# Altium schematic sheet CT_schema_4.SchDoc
size 574 x 363 mm
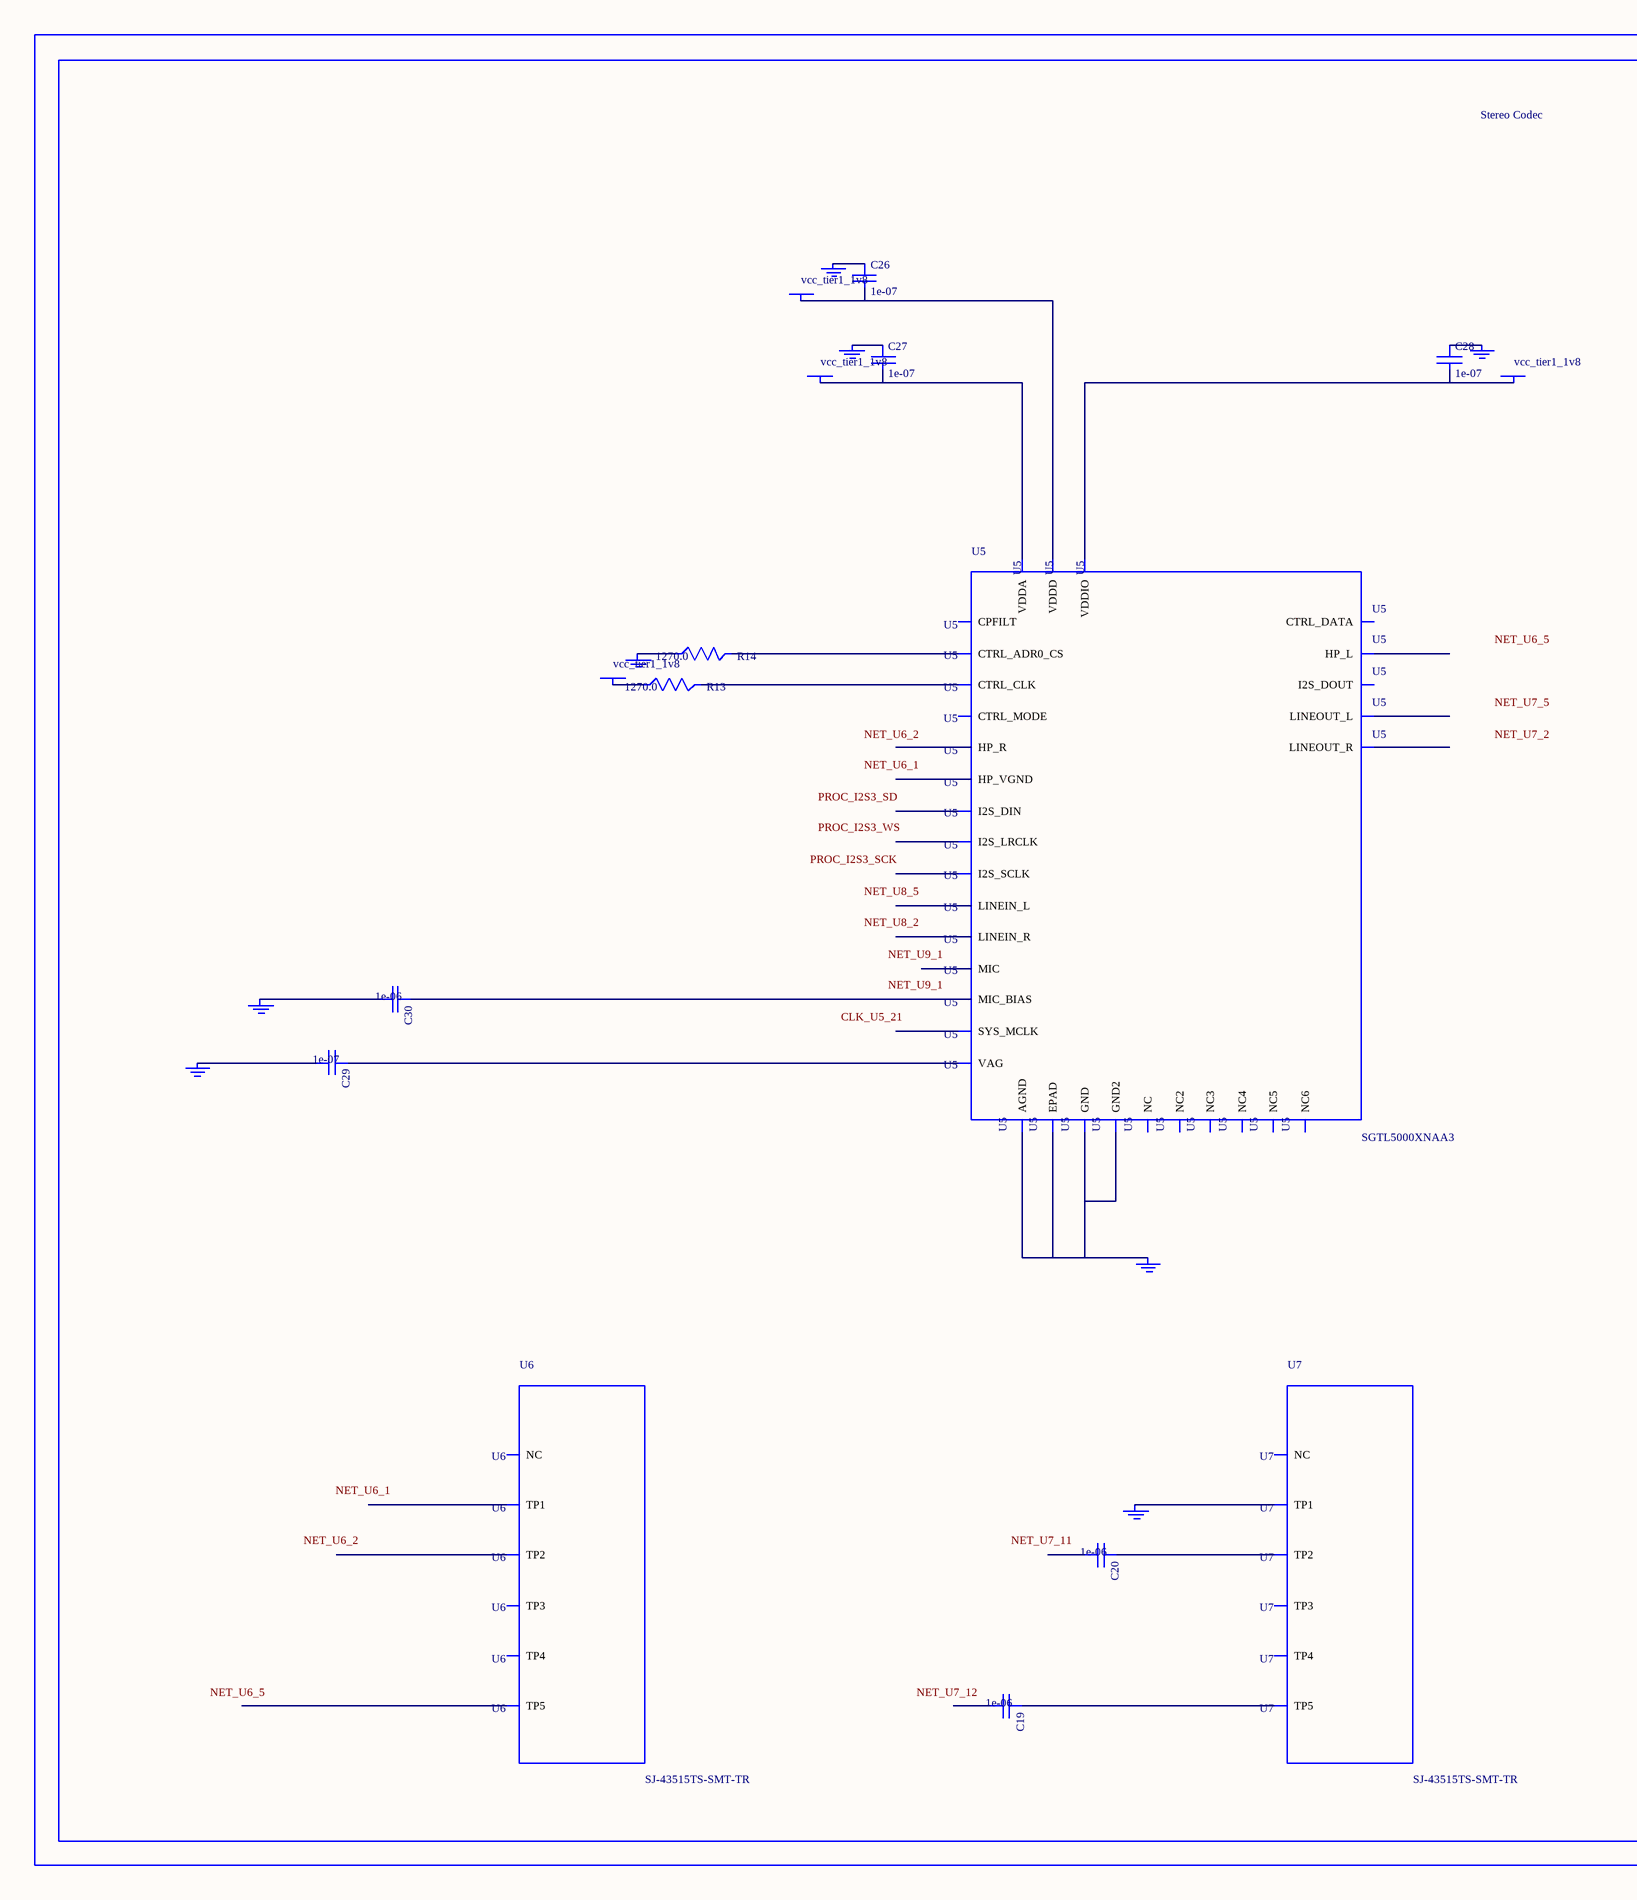
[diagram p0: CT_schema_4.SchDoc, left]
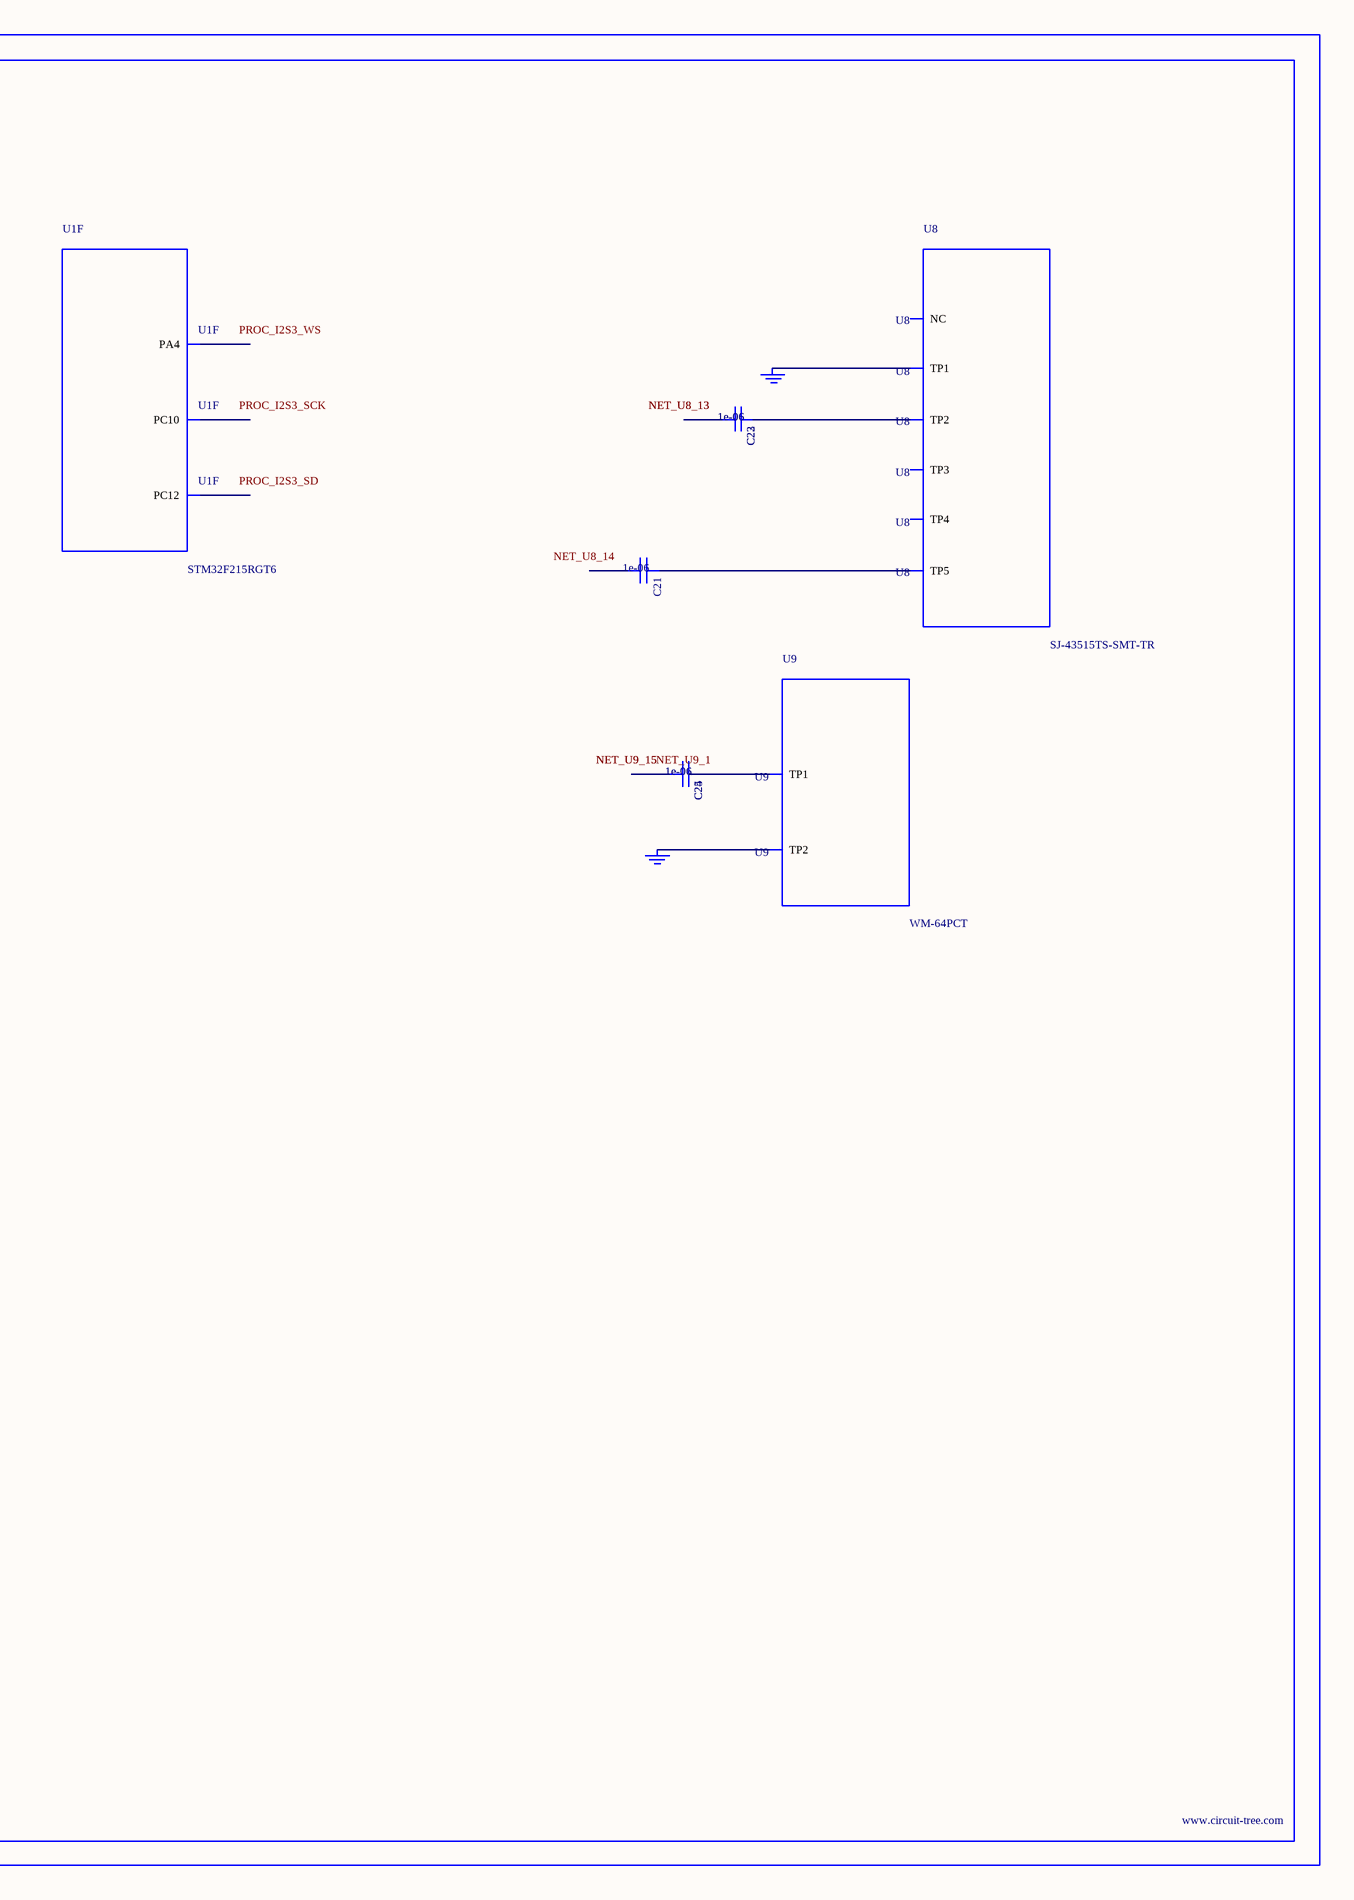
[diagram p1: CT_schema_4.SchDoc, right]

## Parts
BORDER3  (no value)
C19  1e-06  [C0603]
C20  1e-06  [C0603]
C21  1e-06  [C0603]
C22  1e-06  [C0603]
C23  1e-06  [C0603]
C24  1e-06  [C0603]
C25  1e-06  [C0603]
C26  1e-07  [C0402]
C27  1e-07  [C0402]
C28  1e-07  [C0402]
C29  1e-07  [C0402]
C30  1e-06  [C0603]
GND_INSTANCE_3_0  (no value)
GND_INSTANCE_3_1  (no value)
GND_INSTANCE_3_2  (no value)
GND_INSTANCE_3_3  (no value)
GND_INSTANCE_3_4  (no value)
GND_INSTANCE_3_5  (no value)
GND_INSTANCE_3_6  (no value)
GND_INSTANCE_3_7  (no value)
GND_INSTANCE_3_8  (no value)
GND_INSTANCE_3_9  (no value)
GND_INSTANCE_3_10  (no value)
POWER_INSTANCE_3_0  vcc_tier1_1v8
POWER_INSTANCE_3_1  vcc_tier1_1v8
POWER_INSTANCE_3_2  vcc_tier1_1v8
POWER_INSTANCE_3_3  vcc_tier1_1v8
R13  1270.0  [R0603]
R14  1270.0  [R0603]
U1  STM32F215RGT6  [LQFP64]  (part F of 7)
U5  SGTL5000XNAA3  [QFN-32]
U6  SJ-43515TS-SMT-TR  [SJ-43515TS-SMT-TR]
U7  SJ-43515TS-SMT-TR  [SJ-43515TS-SMT-TR]
U8  SJ-43515TS-SMT-TR  [SJ-43515TS-SMT-TR]
U9  WM-64PCT  [WM-64PC]

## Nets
NetC19_1: C19.1 U7.5(TP5)
NetC20_1: C20.1 U7.2(TP2)
NetC21_1: C21.1 U8.5(TP5)
NetC22_1: C22.1 C23.1 U8.2(TP2)
NetC22_2: C22.2 C23.2
NetC24_1: C24.1 C25.1 U9.1(TP1)
NetC24_2: C24.2 C25.2
NetC26_1: C26.1 GND_INSTANCE_3_5.0(GND)
NetC26_2: C26.2 POWER_INSTANCE_3_3.0(PWR) U5.30(VDDD)
NetC27_1: C27.1 GND_INSTANCE_3_1.0(GND)
NetC27_2: C27.2 POWER_INSTANCE_3_0.0(PWR) U5.5(VDDA)
NetC28_1: C28.1 GND_INSTANCE_3_4.0(GND)
NetC28_2: C28.2 POWER_INSTANCE_3_1.0(PWR) U5.20(VDDIO)
NetC29_1: C29.1 U5.10(VAG)
NetC29_2: C29.2 GND_INSTANCE_3_2.0(GND)
NetC30_1: C30.1 U5.16(MIC_BIAS)
NetC30_2: C30.2 GND_INSTANCE_3_3.0(GND)
NetGND_INSTANCE_3_0_0: GND_INSTANCE_3_0.0(GND) U5.1(GND) U5.3(GND2) U5.7(AGND) U5.EXP(EPAD)
NetGND_INSTANCE_3_6_0: GND_INSTANCE_3_6.0(GND) R14.1
NetGND_INSTANCE_3_7_0: GND_INSTANCE_3_7.0(GND) U7.1(TP1)
NetGND_INSTANCE_3_8_0: GND_INSTANCE_3_8.0(GND) GND_INSTANCE_3_9.0(GND) U8.1(TP1)
NetGND_INSTANCE_3_10_0: GND_INSTANCE_3_10.0(GND) U9.2(TP2)
NetPOWER_INSTANCE_3_2_0: POWER_INSTANCE_3_2.0(PWR) R13.1
NetR13_2: R13.2 U5.29(CTRL_CLK)
NetR14_2: R14.2 U5.31(CTRL_ADR0_CS)

Not connected (* = marked no-connect by the designer): C19 2; C20 2; C21 2; U1 20(PA4) 51(PC10) 53(PC12); U5 2(HP_R) 4(HP_VGND) 6(HP_L) 8(NC) 9(NC2) 11(LINEOUT_R) 12(LINEOUT_L) 13(LINEIN_R) 14(LINEIN_L) 15(MIC) 17(NC3) 18(CPFILT) 19(NC4) 21(SYS_MCLK) 22(NC5) 23(I2S_LRCLK) 24(I2S_SCLK) 25(I2S_DOUT) 26(I2S_DIN) 27(CTRL_DATA) 28(NC6) 32(CTRL_MODE); U6 1(TP1) 2(TP2) 3(TP3) 4(TP4) 5(TP5) 6(NC); U7 3(TP3) 4(TP4) 6(NC); U8 3(TP3) 4(TP4) 6(NC)

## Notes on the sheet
- Labels drawn without touching a wire or pin: CLK_U5_21, NET_U6_1, NET_U6_2, NET_U6_5, NET_U7_2, NET_U7_5, NET_U7_11, NET_U7_12, NET_U8_2, NET_U8_5, NET_U8_14, NET_U9_1, PROC_I2S3_SCK, PROC_I2S3_SD, PROC_I2S3_WS

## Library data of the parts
BORDER3 = BORDER_PAGE3
C19-C25 C30 = C0603C105K3RACTU
C26-C29 = C0402C104K3RACTU
GND_INSTANCE_3_0-GND_INSTANCE_3_10 = GND
POWER_INSTANCE_3_0-POWER_INSTANCE_3_3 = PWR
R13 R14 = RC0603FR-071K27L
